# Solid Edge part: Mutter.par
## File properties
Dokumentum tartalom típus: 0
Last saved by: ahadarics
Revision: 76
Sűrűség: 0,000 kg/m^3
Pontosság: 0,990
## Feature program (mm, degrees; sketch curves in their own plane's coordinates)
base feature "unnamed BaseFeature 1"
thread "unnamed Thread 1"
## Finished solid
Body 1: solid body, 23 faces, 46 edges, 24 vertices.
  Faces by surface: cone 14, plane 8, cylinder 1
  Edges by curve: spline 24, circle 16, line 6
Bounding box of the edges (mm): 6.000 x 19.630 x 17.000, from (0, -9.815, -8.5) to (6, 9.815, 8.5).
Cylindrical faces by radius (mm): R4.3235 x1
Conical faces (half-angle, radius in mm at the cone's reference point): 60 deg R4.6618 x2, 60 deg R9.1575 x12
Planar faces by outward normal: +x 1, +z 1, -x 1, -z 1, oblique 4
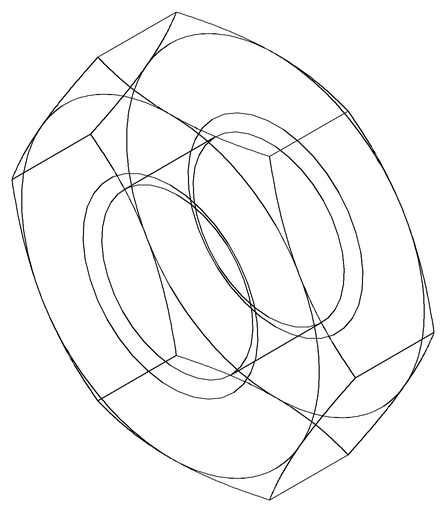
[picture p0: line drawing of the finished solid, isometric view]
